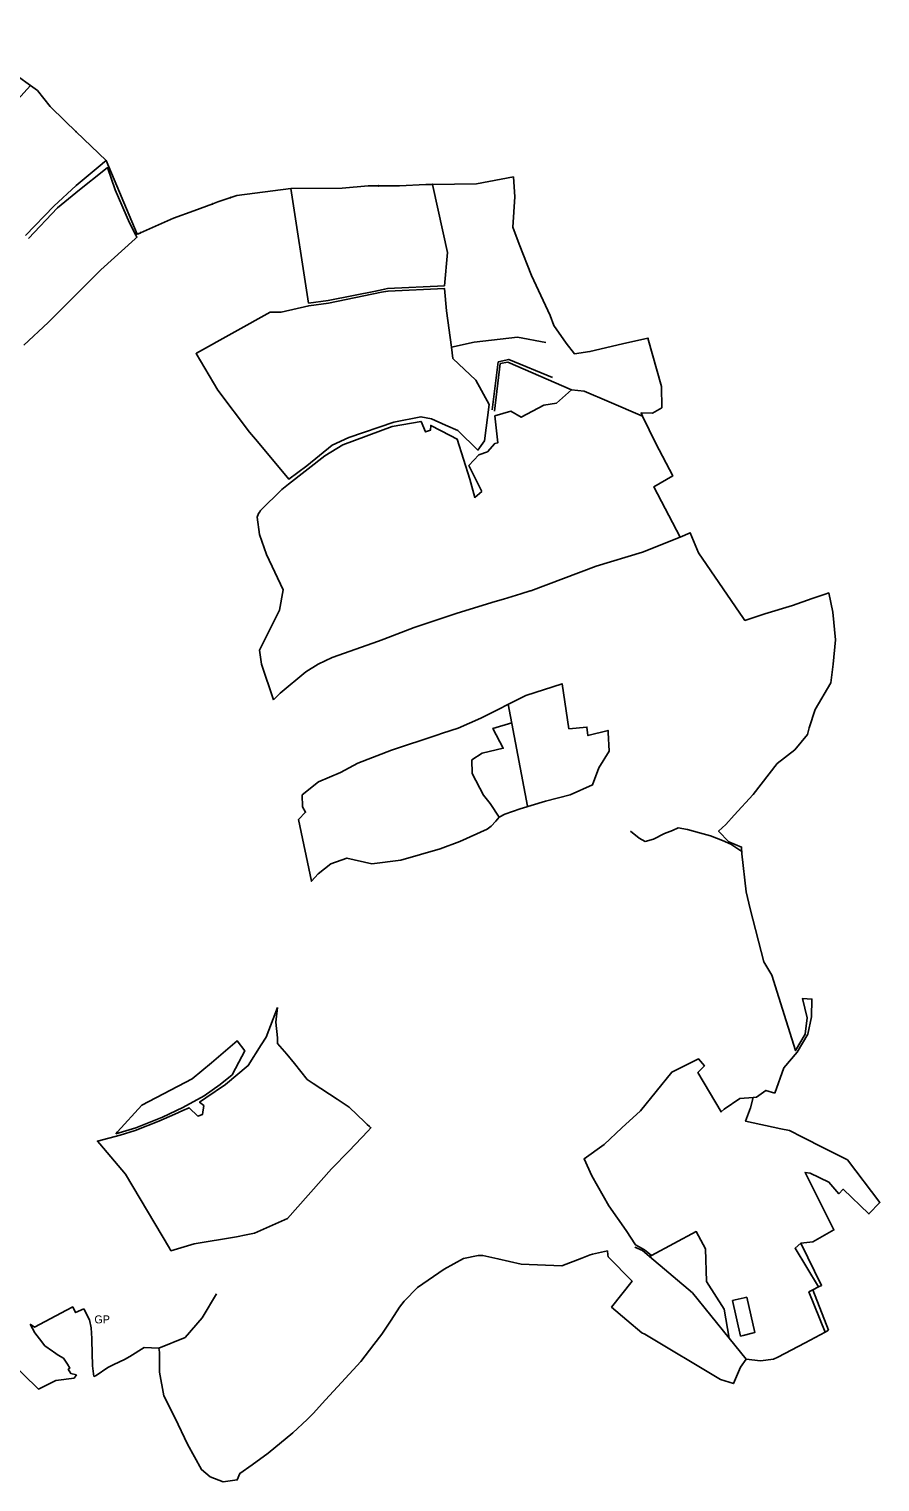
# Model space of a CAD drawing. Extents: x -617038 to -609441, y -1109294 to -1104285.
# Drawn here: x -610504 to -609441, y -1109228 to -1107412 of the extents above; entities that cross this region are included whole.
import ezdxf

# ---------------------------------------------------------------- set-up
doc = ezdxf.new("R2010")
doc.units = 0
for name, color, linetype in [('BOD_SET', 7, 'Continuous'), ('GRA_ZV', 7, 'Continuous'), ('LES_ZV', 7, 'Continuous'), ('Level 255', 7, 'Continuous'), ('OVNE_PRE', 7, 'Continuous'), ('OVNE_SET', 7, 'Continuous'), ('OVNI_SET', 7, 'Continuous'), ('VODA', 7, 'Continuous')]:
    doc.layers.add(name, color=color, linetype=linetype)

msp = doc.modelspace()

# ---------------------------------------------------------------- linework, layer by layer
at = {"layer": 'BOD_SET'}
for p, q in [((-610502.8, -1107481.6), (-610501.8, -1107482.6)), ((-610502.8, -1107482.6), (-610501.8, -1107481.6)), ((-610445.8, -1107539.4), (-610444.8, -1107540.4)), ((-610445.8, -1107540.4), (-610444.8, -1107539.4)), ((-610067.7, -1107607), (-610066.7, -1107608)), ((-610067.7, -1107608), (-610066.7, -1107607)), ((-610000.4, -1107605.3), (-609999.4, -1107606.3)), ((-610000.4, -1107606.3), (-609999.4, -1107605.3)), ((-610275, -1107629.5), (-610274, -1107630.5)), ((-610275, -1107630.5), (-610274, -1107629.5)), ((-610252.5, -1107621.6), (-610251.5, -1107622.6)), ((-610252.5, -1107622.6), (-610251.5, -1107621.6)), ((-610367.8, -1107666.9), (-610366.8, -1107667.9)), ((-610367.8, -1107667.9), (-610366.8, -1107666.9)), ((-610365.4, -1107665.8), (-610364.4, -1107666.8)), ((-610365.4, -1107666.8), (-610364.4, -1107665.8)), ((-609731.1, -1107797.7), (-609730.1, -1107798.7)), ((-609731.1, -1107798.7), (-609730.1, -1107797.7))]:
    msp.add_line(p, q, dxfattribs=at)
at = {"layer": 'GRA_ZV'}
msp.add_line((-610232.7, -1108919), (-610222.1, -1108916.9), dxfattribs=at)
for points in [[(-610563.6, -1107549.3), (-610502.3, -1107482.1), (-610493.5, -1107488.4), (-610477.5, -1107508.5), (-610459.4, -1107526.4), (-610445.3, -1107539.9), (-610407.7, -1107575.9), (-610409.9, -1107577.7), (-610415.2, -1107582.1), (-610445.1, -1107607.3), (-610473.2, -1107633.1), (-610508.5, -1107669.8)], [(-610504.8, -1107673.6), (-610468.5, -1107635.2), (-610440.8, -1107612.4), (-610410.7, -1107588.6), (-610405.9, -1107584.8), (-610396.2, -1107612.8), (-610378.3, -1107653.9), (-610370.7, -1107669.3), (-610369.2, -1107671.9), (-610371.2, -1107673.7), (-610414.1, -1107712.7), (-610480.3, -1107778.4), (-610510.6, -1107806.9)], [(-610155, -1107754.1), (-610176.8, -1107611.1), (-610112.7, -1107610.6), (-610080.1, -1107607.4), (-610067.2, -1107607.5), (-610041.1, -1107607.7), (-610008.1, -1107606), (-609999.9, -1107605.8), (-609999, -1107609.8), (-609981.3, -1107690.9), (-609985, -1107732.4), (-610056, -1107736.1), (-610059.7, -1107736.9), (-610069.1, -1107738.7), (-610130.2, -1107750.9), (-610155, -1107754.1)], [(-610218.7, -1107927.1), (-610228.6, -1107915.3), (-610267.9, -1107863.1), (-610295.3, -1107817), (-610294.6, -1107816.6), (-610202.9, -1107765.4), (-610189.1, -1107765.6), (-610154.5, -1107757.4), (-610129.7, -1107754.1), (-610063.7, -1107740.6), (-610058.4, -1107739.7), (-610055.4, -1107739.1), (-609984.7, -1107736), (-609982.2, -1107763.9), (-609976.2, -1107809.1), (-609974.4, -1107823.6), (-609945.6, -1107850.7), (-609928.9, -1107881.1)], [(-609826.1, -1107862.7), (-609844.9, -1107879.1), (-609860.9, -1107881.6), (-609889.1, -1107896.8), (-609902.1, -1107889.4), (-609921.9, -1107895.1), (-609918.2, -1107928.7), (-609922.1, -1107929.7), (-609931.3, -1107939.9), (-609941.8, -1107943.8), (-609954.4, -1107957.3), (-609938.2, -1107989.8)], [(-609723.3, -1107983.8), (-609699.6, -1107970.2), (-609720.6, -1107929.5), (-609737.3, -1107895.3), (-609779.2, -1107877.4), (-609810.4, -1107864.1), (-609826.1, -1107862.7)], [(-609928.9, -1107881.1), (-609935, -1107926.4), (-609943.2, -1107938), (-609968.1, -1107913.6), (-609983.5, -1107906.7), (-610001, -1107898.7), (-610014.3, -1107896.2), (-610048.3, -1107902.8), (-610104.3, -1107922.3), (-610125.2, -1107931.9), (-610157.1, -1107957.6), (-610179.2, -1107974.4), (-610218.7, -1107927.1)], [(-609938.2, -1107989.8), (-609944.2, -1107994.8), (-609947.1, -1107997.1), (-609953.3, -1107974.4), (-609969.2, -1107924.2), (-609977.7, -1107919.8), (-610002, -1107907.1), (-610002.4, -1107913.2), (-610008.8, -1107915.2), (-610014.2, -1107902.1), (-610050.4, -1107908.4), (-610112, -1107931.3), (-610134.6, -1107944.9), (-610179.8, -1107980.6), (-610188.2, -1107987.3)], [(-610198.5, -1108250), (-610190.2, -1108241.7), (-610158.2, -1108215.1), (-610142.8, -1108205.4), (-610125.1, -1108197.3), (-610067.4, -1108176.9), (-610060.6, -1108174.2), (-610022.8, -1108159.6), (-609969, -1108141.6), (-609921.6, -1108127.2), (-609911.3, -1108124.2), (-609889.4, -1108117.5), (-609877.9, -1108114), (-609877, -1108113.8), (-609795.5, -1108083), (-609737.4, -1108065.5), (-609690.3, -1108046.6), (-609723.3, -1107983.8)], [(-610188.2, -1107987.3), (-610214.7, -1108013.4), (-610215.7, -1108014.9), (-610217.2, -1108017.1), (-610218.8, -1108021.8), (-610216.1, -1108043.5), (-610207.5, -1108068.3), (-610186.5, -1108112.6), (-610191.1, -1108138.2), (-610216.2, -1108187.8), (-610213.7, -1108205.4), (-610198.5, -1108250)], [(-609829.6, -1108286.5), (-609837.9, -1108229.9), (-609883.4, -1108244.7), (-609939.5, -1108273), (-609967.9, -1108285.5), (-609987.2, -1108291.9), (-609994.5, -1108294.4), (-610051, -1108313.1), (-610093, -1108329.3), (-610114.9, -1108341), (-610142.3, -1108352.6), (-610162.8, -1108368.8)], [(-609909.5, -1108393.2), (-609890.4, -1108386.2), (-609858.6, -1108376.6), (-609827.9, -1108369), (-609799.9, -1108356.4), (-609791.9, -1108335.1), (-609779.3, -1108314.1), (-609780.3, -1108290.9), (-609780.4, -1108288.4), (-609805.6, -1108294.7), (-609806.9, -1108284.2), (-609829.6, -1108286.5)], [(-610162.8, -1108368.8), (-610162.2, -1108383.9), (-610158.4, -1108390.6), (-610167.2, -1108399.8), (-610151.2, -1108476.9), (-610142.8, -1108467.7), (-610126.9, -1108455.2), (-610106.9, -1108447.9), (-610075.5, -1108455.1), (-610039.3, -1108450.7), (-609990.3, -1108436.2), (-609965.7, -1108427.3), (-609931.7, -1108411.6), (-609926.5, -1108408.2), (-609920.9, -1108401.6), (-609916.7, -1108396.7), (-609909.5, -1108393.2)], [(-610193.7, -1108634.8), (-610207.9, -1108671.8), (-610213.8, -1108681.2)], [(-610118.9, -1108749.4), (-610148.8, -1108729.6), (-610156.5, -1108724.5), (-610172.2, -1108704.6), (-610182, -1108693.1), (-610193.4, -1108679.7), (-610193.6, -1108672.4), (-610195.8, -1108653.1), (-610193.7, -1108634.8)], [(-610213.8, -1108681.2), (-610230.2, -1108707.2), (-610258.6, -1108730.9), (-610283, -1108747.7), (-610291, -1108753), (-610285.8, -1108757.3), (-610287.4, -1108768.6), (-610293.1, -1108770.4), (-610304.1, -1108759.9), (-610312, -1108763.6), (-610321.8, -1108768), (-610341.9, -1108776.7), (-610371.2, -1108788.2), (-610390.2, -1108794.2), (-610418.6, -1108801.7), (-610415.6, -1108805), (-610383.4, -1108843), (-610328.5, -1108935.6), (-610326.7, -1108938.7), (-610297.5, -1108930), (-610244.6, -1108921.3), (-610232.7, -1108919)], [(-610395.7, -1108792.5), (-610393.4, -1108790), (-610363, -1108756.8), (-610300.1, -1108723.9), (-610276.1, -1108703.9), (-610244, -1108676.3), (-610234.4, -1108688.9), (-610241.9, -1108703.1), (-610250.3, -1108719)], [(-609599, -1108747.2), (-609615.8, -1108748.5), (-609635.5, -1108761.6), (-609639.2, -1108765.2), (-609668.2, -1108715.7), (-609660, -1108707.7), (-609667.3, -1108698.9), (-609701, -1108715.6), (-609740, -1108763.7)], [(-610250.3, -1108719), (-610265, -1108731.1), (-610285.2, -1108745), (-610311.9, -1108759.5), (-610337.1, -1108771.9), (-610370.4, -1108785.2), (-610395.7, -1108792.5)], [(-610078.7, -1108783.4), (-610081.4, -1108781.1), (-610084.5, -1108778.1), (-610104.1, -1108759.1), (-610118.9, -1108749.4)], [(-609740, -1108763.7), (-609763.3, -1108784.9), (-609785.4, -1108805.7), (-609810.5, -1108823.7), (-609800.8, -1108845.1), (-609779.5, -1108882.7), (-609757.7, -1108913.6), (-609746.3, -1108931.2), (-609735.1, -1108937.4), (-609726.1, -1108944.6), (-609670.3, -1108914.7), (-609658.8, -1108936.4)], [(-609539.5, -1108929.3), (-609524.7, -1108927.5), (-609498.3, -1108912.7), (-609534.4, -1108840.8), (-609528, -1108841.8), (-609504.6, -1108853.1), (-609492, -1108867.5), (-609486.6, -1108861.9), (-609454.5, -1108892.6), (-609440.8, -1108878.3), (-609481.4, -1108825.2), (-609510.3, -1108810.5), (-609537.7, -1108796.7), (-609553.8, -1108788.6), (-609564.7, -1108786.2), (-609608.7, -1108776.9), (-609602.4, -1108760.2), (-609599, -1108747.2)], [(-610222.1, -1108916.9), (-610181.1, -1108898.4), (-610126, -1108836.4), (-610104, -1108813.8), (-610080.5, -1108789.1), (-610076.9, -1108784.9), (-610078.7, -1108783.4)], [(-609658.8, -1108936.4), (-609657.5, -1108977.1), (-609635.5, -1109011.9), (-609629.1, -1109048), (-609608.1, -1109074.1), (-609590.1, -1109076.3), (-609573.9, -1109074.4), (-609568.5, -1109071.6), (-609534.2, -1109053.8), (-609509.3, -1109040.4)], [(-609509.3, -1109040.4), (-609529.6, -1108990.1), (-609524.5, -1108987.5), (-609517.4, -1108983.9), (-609546.9, -1108935.5), (-609539.5, -1108929.3)], [(-609624.9, -1109000.9), (-609621.8, -1109000.1), (-609610.5, -1108997.7), (-609607.2, -1108996.9), (-609597.2, -1109041.1), (-609600.3, -1109041.9), (-609611.7, -1109044.5), (-609614.8, -1109045.3), (-609624.9, -1109000.9)]]:
    msp.add_lwpolyline(points, dxfattribs=at)
at = {"layer": 'LES_ZV'}
for p, q in [((-609893.8, -1107796.7), (-609858.4, -1107803.5)), ((-609905.2, -1108255.5), (-609881.1, -1108382.8)), ((-609728.7, -1108946), (-609675, -1108991.4)), ((-609675, -1108991.4), (-609629.1, -1109048))]:
    msp.add_line(p, q, dxfattribs=at)
for points in [[(-609976.2, -1107809.1), (-609947.7, -1107803), (-609893.8, -1107796.7)], [(-609925.3, -1107887.5), (-609917.7, -1107827.6), (-609904.5, -1107824.5), (-609849.9, -1107847.2)], [(-609922.4, -1107889.4), (-609915.3, -1107829.8), (-609905.7, -1107827.9), (-609826.1, -1107862.7)], [(-609900.8, -1108278.8), (-609924.4, -1108285.8), (-609911.5, -1108310.6), (-609937.9, -1108316.6), (-609950.9, -1108325.2), (-609950.4, -1108342.1), (-609936.1, -1108369.1), (-609927.7, -1108379.5), (-609916.7, -1108396.7)], [(-609747.2, -1108934.3), (-609737.6, -1108938.6), (-609728.7, -1108946), (-609726.1, -1108944.6)], [(-610342, -1109060.6), (-610309, -1109047.1), (-610287.6, -1109022.7), (-610269.8, -1108992.4)]]:
    msp.add_lwpolyline(points, dxfattribs=at)
at = {"layer": 'Level 255'}
msp.add_line((-609615.8, -1108748.5), (-609615.8, -1108748.5), dxfattribs=at)
at = {"layer": 'OVNE_PRE'}
for p, q in [((-609898.8, -1107596.3), (-609944.7, -1107605)), ((-610080.1, -1107607.4), (-610112.7, -1107610.6)), ((-609762.6, -1107804.9), (-609730.6, -1107798.2))]:
    msp.add_line(p, q, dxfattribs=at)
for points in [[(-610493.5, -1107488.4), (-610502.3, -1107482.1), (-610518.3, -1107470.7), (-610542.6, -1107444), (-610558.3, -1107428.2), (-610574.7, -1107411.6)], [(-610323.4, -1107648), (-610364.9, -1107666.3), (-610367.3, -1107667.4), (-610369, -1107668.1), (-610407.7, -1107575.9), (-610445.3, -1107539.9), (-610459.4, -1107526.4), (-610477.5, -1107508.5), (-610493.5, -1107488.4)], [(-609762.6, -1107804.9), (-609803.2, -1107814.7), (-609822.6, -1107817.4), (-609832.7, -1107804.1), (-609848.2, -1107782.1), (-609852.7, -1107769.8), (-609876.3, -1107719.8), (-609891.6, -1107680.4), (-609899.3, -1107659.2), (-609897, -1107621.2), (-609898.8, -1107596.3)], [(-610112.7, -1107610.6), (-610176.8, -1107611.1), (-610244.5, -1107619.6), (-610252, -1107622.1), (-610268.2, -1107627.6), (-610274.5, -1107630), (-610298.3, -1107638.7), (-610323.4, -1107648)], [(-609944.7, -1107605), (-609999.9, -1107605.8), (-610008.1, -1107606), (-610041.1, -1107607.7), (-610067.2, -1107607.5), (-610080.1, -1107607.4)]]:
    msp.add_lwpolyline(points, dxfattribs=at)
at = {"layer": 'OVNE_SET'}
msp.add_line((-609509.3, -1109040.4), (-609505, -1109037.9), dxfattribs=at)
for points in [[(-609572.2, -1108741.9), (-609561, -1108710.2), (-609544.2, -1108690.3), (-609530.8, -1108668.1), (-609526.2, -1108646.2), (-609525.7, -1108624.2), (-609537.7, -1108623.6), (-609531.5, -1108647.6), (-609534.2, -1108667.8), (-609546.2, -1108688.6), (-609567.2, -1108622.1), (-609575.9, -1108594.3), (-609585.8, -1108577.4), (-609602.8, -1108511.3), (-609607.9, -1108489.9), (-609613.5, -1108442.4), (-609613.6, -1108434.2), (-609629.5, -1108427.6), (-609642.4, -1108414.4), (-609633.4, -1108405.9), (-609622.9, -1108394.3), (-609599.2, -1108368.4), (-609569.1, -1108329.5), (-609547.2, -1108312.4), (-609531.1, -1108293.6), (-609529.3, -1108285.2), (-609521.7, -1108262.3), (-609502, -1108228.7), (-609499.3, -1108205.5), (-609496.3, -1108175.1), (-609499.5, -1108140.4), (-609504.8, -1108116.4), (-609509.2, -1108117.9), (-609525.3, -1108123.5), (-609549.9, -1108132), (-609584.6, -1108142.6), (-609609.5, -1108150.8), (-609611.1, -1108148.5), (-609667.5, -1108066.3), (-609677.9, -1108041.3), (-609690.3, -1108046.6), (-609723.3, -1107983.8), (-609699.6, -1107970.2), (-609720.6, -1107929.5), (-609737.3, -1107895.3), (-609739.2, -1107891.4), (-609725, -1107891.9), (-609713.1, -1107884.9), (-609713.6, -1107858.4), (-609730.6, -1107798.2)], [(-609505, -1109037.9), (-609524.5, -1108987.5), (-609517.4, -1108983.9), (-609513.7, -1108982), (-609539.5, -1108929.3), (-609524.7, -1108927.5), (-609498.3, -1108912.7), (-609534.4, -1108840.8), (-609528, -1108841.8), (-609504.6, -1108853.1), (-609492, -1108867.5), (-609486.6, -1108861.9), (-609454.5, -1108892.6), (-609440.8, -1108878.3), (-609481.4, -1108825.2), (-609510.3, -1108810.5), (-609537.7, -1108796.7), (-609553.8, -1108788.6), (-609564.7, -1108786.2), (-609608.7, -1108776.9), (-609602.4, -1108760.2), (-609599, -1108747.2), (-609595.1, -1108746.9), (-609583.3, -1108738.4), (-609572.2, -1108741.9)], [(-610133.5, -1109125), (-610113.7, -1109103.4), (-610089.5, -1109077), (-610073.3, -1109055.9), (-610063, -1109042.8), (-610051.6, -1109025.6), (-610041.1, -1109009.1), (-610035.4, -1109001.8), (-610018.5, -1108984.7), (-609985.1, -1108961.9), (-609961.1, -1108948.3), (-609942.8, -1108944.8), (-609936.8, -1108944.8), (-609918.2, -1108948.7), (-609889.1, -1108955.4), (-609838.1, -1108957.4), (-609813.2, -1108947.9), (-609802.9, -1108943.9)], [(-609802.9, -1108943.9), (-609800, -1108942.8), (-609781.4, -1108938.9)], [(-609781.4, -1108938.9), (-609780.8, -1108943.9), (-609780.3, -1108946.2), (-609750.5, -1108976.6), (-609776.2, -1109009.2), (-609757, -1109025.5), (-609738.1, -1109041.2), (-609734.7, -1109042.9), (-609639.9, -1109099.7), (-609623.8, -1109104.7), (-609615.2, -1109084.2), (-609608.1, -1109074.1), (-609590.1, -1109076.3), (-609573.9, -1109074.4), (-609568.5, -1109071.6)], [(-609568.5, -1109071.6), (-609534.2, -1109053.8), (-609509.3, -1109040.4)], [(-610444.9, -1109093.9), (-610447.8, -1109098), (-610470.6, -1109100.9), (-610486.2, -1109108.7), (-610492.1, -1109111.6), (-610530.2, -1109074.7), (-610553.1, -1109060.6), (-610558, -1109063.4), (-610559.1, -1109063.9), (-610562, -1109065.2), (-610564, -1109066.1), (-610571.5, -1109072.5), (-610583.4, -1109081), (-610592.3, -1109087.1), (-610595.2, -1109096), (-610610.8, -1109086.2), (-610621.8, -1109092.7), (-610632.7, -1109099.1), (-610635.1, -1109100.5), (-610640.8, -1109104.2)], [(-610422.9, -1109095.7), (-610420.3, -1109094.5), (-610405.6, -1109084.7), (-610398.2, -1109080.7), (-610384.7, -1109074.7), (-610377.9, -1109071), (-610360.1, -1109059.5), (-610342, -1109060.6), (-610340.8, -1109065.6), (-610341.1, -1109090.3), (-610335.5, -1109120), (-610321.5, -1109148), (-610306, -1109180.3), (-610288.6, -1109212.2), (-610277.6, -1109221.2), (-610261.5, -1109227.7), (-610243.8, -1109225.1), (-610240.5, -1109217.1), (-610225.4, -1109206.5), (-610205.1, -1109191.8), (-610174.2, -1109166.4), (-610156.6, -1109149.8), (-610149, -1109142), (-610133.5, -1109125)]]:
    msp.add_lwpolyline(points, dxfattribs=at)
at = {"layer": 'OVNI_SET'}
for points in [[(-610435.4, -1109011.2), (-610445.8, -1109016.1), (-610449.4, -1109008.9), (-610457.1, -1109012.9), (-610497.2, -1109034.1), (-610502.8, -1109030.4)], [(-610425.4, -1109050.4), (-610425.4, -1109048.4), (-610426.4, -1109035), (-610428.6, -1109024.9), (-610435.4, -1109011.2)], [(-610502.8, -1109030.4), (-610496.6, -1109041.3), (-610491, -1109048.7), (-610484.2, -1109057.4), (-610474.7, -1109064.3)], [(-610422.9, -1109095.7), (-610424.6, -1109082.5), (-610425.4, -1109050.4)], [(-610474.7, -1109064.3), (-610473.4, -1109065.2), (-610467.5, -1109069.4), (-610461, -1109073), (-610456, -1109080.6), (-610452.9, -1109085.4), (-610455.1, -1109086.8), (-610451.6, -1109092.2), (-610444.9, -1109093.9)]]:
    msp.add_lwpolyline(points, dxfattribs=at)
at = {"layer": 'VODA'}
msp.add_lwpolyline([(-609752.3, -1108414.3), (-609741.7, -1108422.8), (-609734.3, -1108427), (-609723.6, -1108424.3), (-609709.9, -1108417.1), (-609699.9, -1108413.3), (-609692.9, -1108410.1), (-609681.3, -1108412.2), (-609666.2, -1108416.2), (-609652.5, -1108420), (-609637.7, -1108425.8), (-609627.2, -1108430.3), (-609617.2, -1108437.3), (-609613.4, -1108439.6)], dxfattribs=at)

# ---------------------------------------------------------------- texts
at = {"layer": 'OVNE_SET'}
msp.add_text('GP', height=10, dxfattribs=at).set_placement((-610422.3, -1109029.5))

doc.saveas('drawing.dxf')
